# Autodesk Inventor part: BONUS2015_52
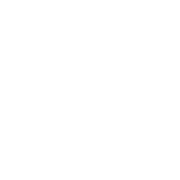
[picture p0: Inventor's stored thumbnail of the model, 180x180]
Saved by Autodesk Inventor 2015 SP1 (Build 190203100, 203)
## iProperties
Created: 2015-05
Part Number: BONUS2015_52
Material: Generisch
Document SubType Name: Modeling
Density: 1 g/cm^3
Appearance: Vorgabe
xx: 52
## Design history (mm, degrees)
